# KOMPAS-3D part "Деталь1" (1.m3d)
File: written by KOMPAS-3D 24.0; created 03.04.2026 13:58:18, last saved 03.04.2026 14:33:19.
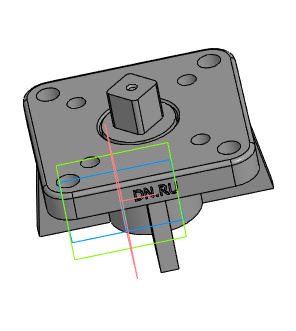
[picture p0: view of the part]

Document properties: Автор: R2D2; Полное имя файла: E:\Работа\Зайцев\Аксессуары для пневмоприводов\Ручной дублер DN.ru\MON2-450-T28-ISO Ручной дублер DN.ru\исходные материалы\1.m3d

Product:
- Body: Тело 2  | qty 1
    Масса: 1.480657
- Part/product: Деталь1
    Масса: 10.922817
    additional columns: Типовые

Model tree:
1. Операция без истории:1
2. Эскиз:1  (with: Ребро.Операция без истории:1)
3. Элемент выдавливания:1
     Расстояние 1 = 500
4. Эскиз:2  (with: Грань.Операция без истории:1, Ребро.Операция без истории:1)
5. Элемент выдавливания:2
6. Эскиз:3  (with: Грань.Операция без истории:1, Ребро.Операция без истории:1)
7. Элемент выдавливания:3
     Расстояние 1 = 33
8. Эскиз:4  (with: Ребро.Операция без истории:1, Ребро.Элемент выдавливания:3)
9. Элемент выдавливания:4
     Расстояние 1 = 8
10. Массив по концентрической сетке:1  (with: Элемент выдавливания:4, Эскиз:4, Грань.Элемент выдавливания:3)  (4 pattern instances)
     Шаг 2 = 360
